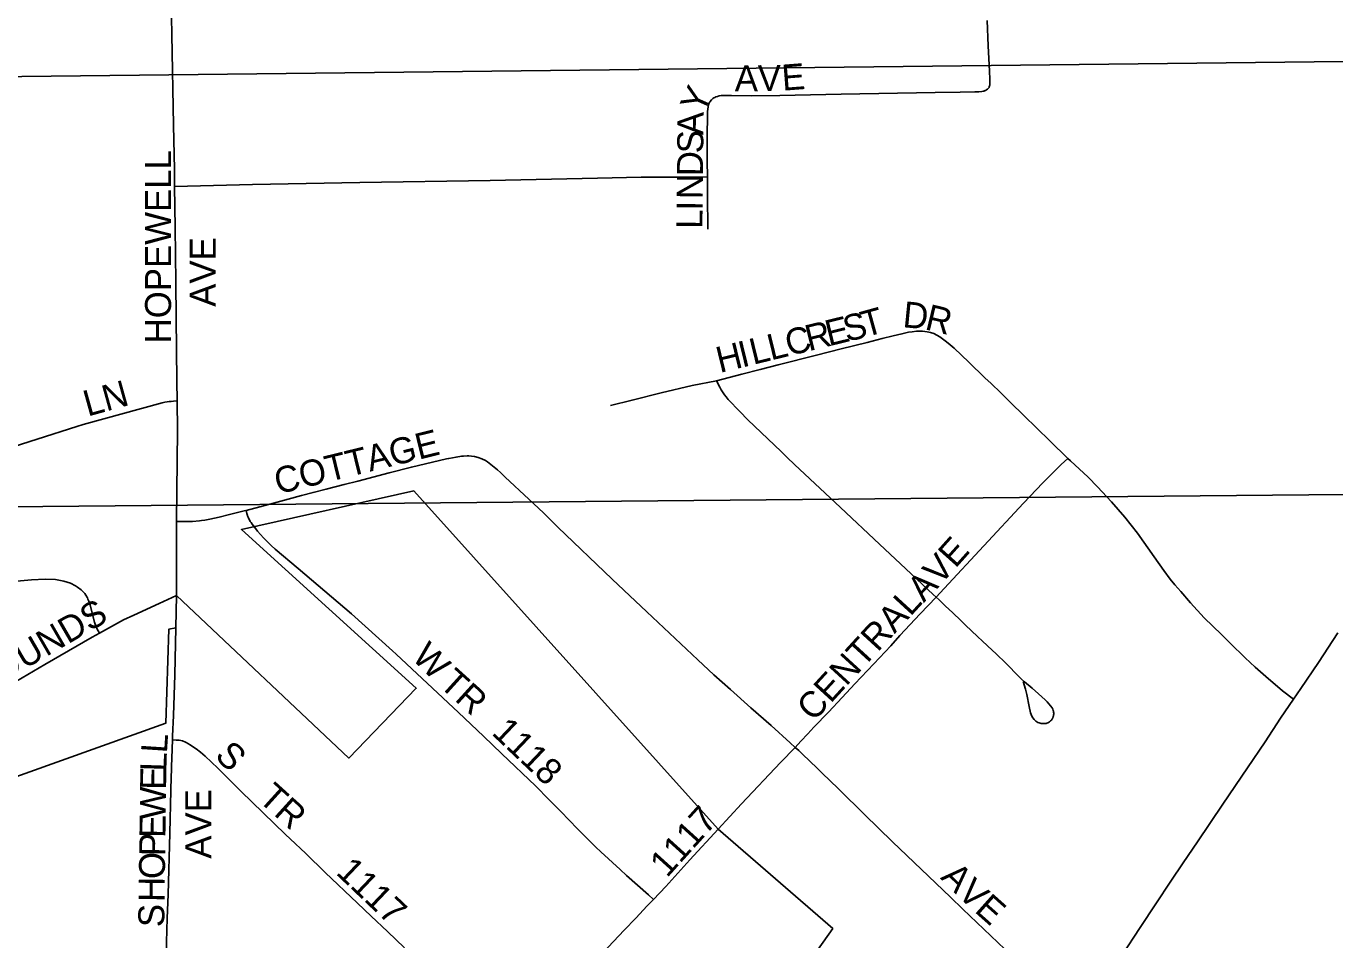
# Model space of a CAD drawing. Extents: x 0 to 34, y 0 to 22.
# Drawn here: x 5.2041 to 5.4422, y 18.3375 to 18.5038 of the extents above; entities that cross this region are included whole.
import ezdxf

# ---------------------------------------------------------------- set-up
doc = ezdxf.new("R2010")
doc.units = 0
for name, color, linetype in [('GM_X_City_Street', 7, 'Continuous'), ('GM_X_City_Street_Text', 7, 'Continuous'), ('GM_X_Corporation', 7, 'Continuous'), ('GM_X_Section', 7, 'Continuous'), ('GM_X_State_Route', 7, 'Continuous')]:
    doc.layers.add(name, color=color, linetype=linetype)

msp = doc.modelspace()

# ---------------------------------------------------------------- linework, layer by layer
at = {"layer": 'GM_X_City_Street'}
for points in [[(5.23109, 18.47463), (5.23105, 18.47771), (5.23086, 18.48578), (5.2306, 18.50224), (5.23035, 18.51491), (5.23033, 18.52348)], [(5.32805, 18.47635), (5.32797, 18.47924), (5.32797, 18.4837), (5.32802, 18.48767), (5.32805, 18.48826), (5.32808, 18.48868), (5.32813, 18.48907), (5.32817, 18.48927), (5.32822, 18.48944), (5.32831, 18.48967), (5.32836, 18.4898), (5.32845, 18.48995), (5.32853, 18.49008), (5.32874, 18.49034), (5.32887, 18.49048), (5.32894, 18.49055), (5.32903, 18.49062), (5.32919, 18.49073), (5.32935, 18.49082), (5.32954, 18.4909), (5.32984, 18.491), (5.33017, 18.49108), (5.33052, 18.49114), (5.3313, 18.49118), (5.3324, 18.49116), (5.33599, 18.49112), (5.3412, 18.49114), (5.35237, 18.4914), (5.36947, 18.4917), (5.37403, 18.49174), (5.37668, 18.49181), (5.37743, 18.49185), (5.37793, 18.49191), (5.3782, 18.49195), (5.37832, 18.49197), (5.37843, 18.492), (5.37854, 18.49205), (5.37863, 18.49209), (5.37878, 18.49218), (5.37885, 18.49223), (5.37897, 18.49233), (5.37915, 18.49249), (5.37926, 18.49264), (5.37931, 18.49275), (5.37936, 18.49289), (5.37938, 18.49297), (5.37941, 18.49317), (5.37942, 18.49335), (5.37942, 18.49368), (5.3794, 18.49412), (5.37932, 18.4956), (5.37909, 18.50017), (5.37894, 18.50481)], [(5.23109, 18.47463), (5.24526, 18.47497), (5.26478, 18.47533), (5.28848, 18.47569), (5.30805, 18.47614), (5.31598, 18.47629), (5.32367, 18.47633), (5.32805, 18.47635)], [(5.32808, 18.46682), (5.32805, 18.47302), (5.32805, 18.47635)], [(5.23154, 18.43559), (5.23151, 18.43918), (5.23137, 18.45068), (5.23132, 18.4572), (5.23121, 18.46715), (5.23109, 18.47463)], [(5.32968, 18.43927), (5.33311, 18.44014), (5.3343, 18.44046), (5.3376, 18.44131), (5.34091, 18.44214), (5.34789, 18.44393), (5.35236, 18.44505), (5.35707, 18.44623), (5.35984, 18.44692), (5.36184, 18.44741), (5.36341, 18.44777), (5.36462, 18.44807), (5.36529, 18.44818), (5.36606, 18.44826), (5.36662, 18.44829), (5.36717, 18.44829), (5.36799, 18.44819), (5.36862, 18.44805), (5.3692, 18.44783), (5.36977, 18.44755), (5.37029, 18.44722), (5.37129, 18.44652), (5.37184, 18.4461), (5.37291, 18.44519), (5.37559, 18.44262), (5.37851, 18.43982), (5.37964, 18.43878), (5.38141, 18.43704), (5.38317, 18.43529), (5.38562, 18.43291), (5.3903, 18.42834), (5.39359, 18.42514)], [(5.31041, 18.43474), (5.31431, 18.43575), (5.31962, 18.43704), (5.32526, 18.43841), (5.32968, 18.43927)], [(5.36965, 18.39989), (5.36912, 18.4004), (5.3651, 18.40414), (5.35931, 18.4095), (5.35222, 18.41621), (5.34387, 18.424), (5.34254, 18.4253), (5.34143, 18.42637), (5.33539, 18.43215), (5.3339, 18.43365), (5.33179, 18.43587), (5.33142, 18.43632), (5.33114, 18.43668), (5.33075, 18.43727), (5.33052, 18.43762), (5.33027, 18.43807), (5.32968, 18.43927)], [(5.15883, 18.41028), (5.16291, 18.41201), (5.16465, 18.41274), (5.16787, 18.41411), (5.17301, 18.41628), (5.18117, 18.41967), (5.18269, 18.42027), (5.18973, 18.42308), (5.19879, 18.42632), (5.21328, 18.43093), (5.21446, 18.43127), (5.22885, 18.43523), (5.22932, 18.43534), (5.22971, 18.43542), (5.23007, 18.43547), (5.23047, 18.4355), (5.23088, 18.43553), (5.23154, 18.43559)], [(5.23145, 18.41364), (5.23159, 18.43018), (5.23154, 18.43559)], [(5.24413, 18.41566), (5.24905, 18.41697), (5.25173, 18.4177), (5.2542, 18.41838), (5.25629, 18.41894), (5.25864, 18.41955), (5.26193, 18.42037), (5.26443, 18.421), (5.27012, 18.42248), (5.27417, 18.42354), (5.28054, 18.42505), (5.28096, 18.42514), (5.28229, 18.42538), (5.28326, 18.42552), (5.28363, 18.42555), (5.28431, 18.42559), (5.28461, 18.42558), (5.2851, 18.42554), (5.28567, 18.42545), (5.28634, 18.42528), (5.28699, 18.42505), (5.28763, 18.42472), (5.28801, 18.42448), (5.28831, 18.42426), (5.28983, 18.42304), (5.29038, 18.42256), (5.29124, 18.42174), (5.29554, 18.41772), (5.29821, 18.4152), (5.30083, 18.4126), (5.3107, 18.40319), (5.3128, 18.40115), (5.31698, 18.3972), (5.32625, 18.38849), (5.32922, 18.38577), (5.33222, 18.38308), (5.33591, 18.37978), (5.33965, 18.37651), (5.34307, 18.3734), (5.34401, 18.37254)], [(5.36965, 18.39989), (5.37111, 18.40148), (5.38555, 18.417), (5.38902, 18.42067), (5.39177, 18.42342), (5.39237, 18.42401), (5.39359, 18.42514)], [(5.39359, 18.42514), (5.39409, 18.42466), (5.39727, 18.4217), (5.39902, 18.41994), (5.40156, 18.41725), (5.40398, 18.41445), (5.40629, 18.41155), (5.40932, 18.40722), (5.41104, 18.40475), (5.41223, 18.40318), (5.41306, 18.40215), (5.41413, 18.40089), (5.41592, 18.39887), (5.41841, 18.39614), (5.42158, 18.39307), (5.42314, 18.39153), (5.42589, 18.38886), (5.42771, 18.38716), (5.42965, 18.38543), (5.43264, 18.38287), (5.43465, 18.38131)], [(5.23145, 18.41364), (5.23204, 18.41364), (5.23317, 18.41364), (5.23432, 18.41367), (5.23563, 18.41378), (5.23597, 18.41382), (5.23658, 18.41391), (5.23749, 18.41406), (5.23918, 18.41442), (5.24106, 18.4149), (5.24375, 18.41558), (5.24413, 18.41566)], [(5.24413, 18.41566), (5.24425, 18.41512), (5.24429, 18.41495), (5.24434, 18.41476), (5.24437, 18.41466), (5.2444, 18.41457), (5.24446, 18.41445), (5.24455, 18.41427), (5.2447, 18.41395), (5.24486, 18.41366), (5.24499, 18.41345), (5.24519, 18.41314), (5.24566, 18.41254), (5.24618, 18.4119), (5.24726, 18.4107), (5.24795, 18.40999), (5.24865, 18.40928), (5.24941, 18.40859), (5.25358, 18.40513), (5.26327, 18.39686), (5.27072, 18.39015), (5.27142, 18.38949), (5.28276, 18.37889), (5.28727, 18.3746)], [(5.23142, 18.4002), (5.23143, 18.40065), (5.23141, 18.40905), (5.23145, 18.41364)], [(5.1998, 18.40254), (5.20507, 18.40306), (5.20755, 18.40318), (5.20942, 18.40309), (5.21094, 18.40282), (5.21212, 18.40241), (5.21303, 18.40194), (5.21344, 18.40168), (5.21409, 18.40119), (5.21434, 18.40096), (5.21474, 18.40053), (5.21495, 18.40023), (5.21521, 18.39979), (5.21532, 18.39952), (5.21546, 18.39917), (5.2157, 18.39843), (5.21652, 18.39533), (5.21664, 18.39496), (5.21686, 18.39439), (5.21702, 18.39404), (5.21718, 18.39375), (5.21744, 18.39335)], [(5.22366, 18.39662), (5.22828, 18.39875), (5.23142, 18.4002)], [(5.23071, 18.37392), (5.23073, 18.3746), (5.23086, 18.37833), (5.23113, 18.38578), (5.23132, 18.39433), (5.23142, 18.4002)], [(5.34401, 18.37254), (5.34505, 18.3737), (5.34629, 18.375), (5.34739, 18.37621), (5.35006, 18.37899), (5.35252, 18.38161), (5.35483, 18.38412), (5.35828, 18.38778), (5.36138, 18.39103), (5.36306, 18.39289), (5.36675, 18.39687), (5.36965, 18.39989)], [(5.38546, 18.38457), (5.3859, 18.38313), (5.38615, 18.38216), (5.38654, 18.38001), (5.38682, 18.37885), (5.38707, 18.37823), (5.38725, 18.37791), (5.38747, 18.3776), (5.38777, 18.37732), (5.38812, 18.3771), (5.38839, 18.377), (5.38873, 18.37692), (5.38915, 18.37688), (5.38934, 18.37688), (5.38963, 18.37693), (5.38977, 18.37697), (5.38993, 18.37703), (5.39007, 18.3771), (5.39027, 18.37722), (5.39046, 18.37736), (5.39061, 18.37752), (5.39075, 18.37772), (5.39084, 18.3779), (5.39094, 18.37815), (5.39098, 18.37827), (5.39099, 18.37833), (5.39101, 18.37846), (5.39103, 18.37862), (5.39103, 18.37881), (5.39101, 18.37896), (5.39098, 18.37915), (5.39095, 18.37929), (5.39087, 18.37949), (5.39072, 18.37976), (5.39046, 18.38011), (5.38981, 18.38082), (5.38947, 18.38118), (5.38829, 18.3823), (5.38708, 18.38335), (5.3857, 18.38449), (5.38518, 18.38496), (5.38477, 18.38538), (5.38231, 18.38786), (5.38054, 18.38959), (5.37986, 18.39022), (5.37808, 18.3919), (5.37718, 18.39271), (5.37609, 18.39378), (5.37499, 18.39479), (5.37413, 18.39563), (5.37266, 18.39701), (5.3713, 18.3983), (5.37019, 18.39938), (5.36965, 18.39989)], [(5.21744, 18.39335), (5.22067, 18.39518), (5.22177, 18.39575), (5.22366, 18.39662)], [(5.19889, 18.38266), (5.20232, 18.38463), (5.20746, 18.38763), (5.21611, 18.3926), (5.21744, 18.39335)], [(5.23181, 18.32496), (5.23143, 18.32555), (5.23108, 18.32616), (5.2308, 18.32675), (5.23053, 18.32748), (5.23031, 18.32822), (5.2301, 18.32911), (5.2299, 18.33018), (5.22981, 18.33083), (5.22974, 18.33157), (5.22963, 18.33388), (5.22961, 18.3371), (5.22973, 18.34147), (5.2299, 18.3458), (5.23022, 18.35696), (5.2304, 18.36471), (5.23048, 18.3672), (5.23051, 18.36844), (5.23052, 18.36906), (5.23059, 18.37059), (5.23071, 18.37392)], [(5.23071, 18.37392), (5.23137, 18.37388), (5.23176, 18.37386), (5.23194, 18.37384), (5.2322, 18.3738), (5.23251, 18.37373), (5.23265, 18.37368), (5.23297, 18.37356), (5.23318, 18.37345), (5.23359, 18.37322), (5.23379, 18.37309), (5.23501, 18.3723), (5.23581, 18.37168), (5.23662, 18.37098), (5.23892, 18.36877), (5.24316, 18.36457), (5.25127, 18.3567), (5.2521, 18.35593), (5.25496, 18.35322), (5.25848, 18.3498), (5.26439, 18.3442), (5.26686, 18.34185), (5.26979, 18.33907), (5.2729, 18.33607)], [(5.28727, 18.3746), (5.29063, 18.37139), (5.29672, 18.36557), (5.29926, 18.36304), (5.30136, 18.36088), (5.3044, 18.35773), (5.30648, 18.35563), (5.30775, 18.35438), (5.30862, 18.35358), (5.31216, 18.35031), (5.31333, 18.34924), (5.31731, 18.34571), (5.31822, 18.3449)], [(5.32998, 18.35768), (5.3342, 18.36227), (5.34134, 18.36982), (5.34401, 18.37254)], [(5.34401, 18.37254), (5.34464, 18.37196), (5.34532, 18.37133), (5.34797, 18.36876), (5.34908, 18.3677), (5.3502, 18.36663), (5.35199, 18.36491), (5.35663, 18.36036), (5.36172, 18.35538), (5.36822, 18.34915), (5.37226, 18.3453), (5.37449, 18.34313), (5.38214, 18.33587), (5.38327, 18.33481), (5.38735, 18.33103), (5.38872, 18.32979), (5.39099, 18.32771), (5.39266, 18.32638), (5.39411, 18.32534), (5.39537, 18.32459), (5.39631, 18.32403)], [(5.31822, 18.3449), (5.32045, 18.34722), (5.32484, 18.35207), (5.32998, 18.35768)], [(5.29316, 18.32001), (5.2938, 18.32024), (5.29417, 18.32043), (5.29471, 18.32079), (5.29555, 18.32142), (5.29625, 18.32198), (5.29768, 18.32335), (5.29955, 18.32544), (5.30187, 18.32791), (5.30334, 18.32942), (5.30553, 18.3316), (5.30994, 18.33621), (5.31288, 18.33929), (5.31498, 18.34148), (5.31707, 18.34371), (5.31822, 18.3449)]]:
    msp.add_lwpolyline(points, dxfattribs=at)
at = {"layer": 'GM_X_Corporation'}
msp.add_lwpolyline([(5.33764, 18.3209), (5.35084, 18.33959), (5.32998, 18.35768), (5.27459, 18.41921), (5.24324, 18.41219), (5.27506, 18.38332), (5.2628, 18.37062), (5.23142, 18.4002), (5.23133, 18.39433), (5.23006, 18.39408), (5.22948, 18.37696), (5.16013, 18.35215)], dxfattribs=at)
at = {"layer": 'GM_X_Section'}
for points in [[(4.96887, 18.91739), (5.22048, 18.91682), (5.36618, 18.91648), (5.36674, 18.86475), (5.0257, 18.8658), (5.02156, 18.49258), (5.46515, 18.49757), (5.46379, 18.41876), (4.95692, 18.41406)], [(5.46396, 18.4161), (5.4644, 17.92291), (5.46435, 17.9159), (4.95614, 17.90875), (4.95692, 18.41406), (5.46379, 18.41876)]]:
    msp.add_lwpolyline(points, close=True, dxfattribs=at)
at = {"layer": 'GM_X_State_Route'}
msp.add_lwpolyline([(5.40344, 18.33469), (5.40675, 18.33979), (5.4096, 18.34409), (5.41232, 18.34822), (5.41459, 18.35153), (5.41717, 18.35539), (5.42182, 18.36224), (5.42626, 18.36885), (5.4295, 18.37357), (5.43226, 18.37786), (5.43465, 18.38131), (5.43601, 18.38329), (5.43918, 18.38798), (5.44274, 18.39337)], dxfattribs=at)

# ---------------------------------------------------------------- texts
at = {"layer": 'GM_X_City_Street_Text'}
for s, height, rotation, p in [('A', 0.00473, 0.0874, (5.333, 18.49194)), ('V', 0.00473, 0.9054, (5.33723, 18.49194)), ('E', 0.00473, 4.4187, (5.34172, 18.49202)), ('Y', 0.00473, 66.1041, (5.32722, 18.48762)), ('A', 0.00473, 89.3846, (5.32728, 18.48395)), ('S', 0.00473, 89.3928, (5.32725, 18.48062)), ('HOPEWELL', 0.004735, 90, (5.23044, 18.44605)), ('D', 0.00473, 89.3846, (5.3272, 18.47645)), ('N', 0.00473, 89.3846, (5.32716, 18.47228)), ('L', 0.00473, 89.3989, (5.3271, 18.46687)), ('I', 0.00473, 89.3882, (5.32714, 18.4702)), ('AVE', 0.004735, 90, (5.23858, 18.45271)), ('T', 0.00473, 15.4331, (5.35672, 18.44714)), ('D', 0.00473, 354.483, (5.36344, 18.44902)), ('R', 0.00473, 346.4174, (5.36742, 18.44865)), ('E', 0.00473, 13.738, (5.3501, 18.44551)), ('S', 0.00473, 13.7685, (5.35334, 18.4463)), ('L', 0.00473, 13.7438, (5.33958, 18.44294)), ('C', 0.00473, 13.7572, (5.34282, 18.44373)), ('R', 0.00473, 13.7536, (5.34646, 18.44462)), ('H', 0.00473, 13.75, (5.33027, 18.44066)), ('I', 0.00473, 13.7544, (5.33432, 18.44165)), ('L', 0.00473, 13.738, (5.33634, 18.44215)), ('LN', 0.004735, 15.526, (5.21526, 18.43272)), ('COTTAGE', 0.004735, 13.824, (5.24988, 18.41858)), ('E', 0.00473, 48.1851, (5.37313, 18.40501)), ('V', 0.00473, 48.0297, (5.37034, 18.4019)), ('A', 0.00473, 46.6233, (5.36739, 18.39878)), ('CENTRAL', 0.004735, 47.4873, (5.34734, 18.37707)), ('FAIRGROUNDS', 0.0047348, 30.0928, (5.1788, 18.37224)), ('W', 0.00473, 315.0121, (5.27404, 18.38876)), ('TR', 0.004735, 317.8608, (5.27901, 18.38379)), ('1118', 0.004735, 316.4679, (5.28861, 18.37503)), ('L', 0.00473, 86.3367, (5.22968, 18.37142)), ('S', 0.00473, 315, (5.23821, 18.37084)), ('L', 0.00473, 88.1145, (5.22957, 18.36812)), ('E', 0.00473, 89.2077, (5.22953, 18.36481)), ('W', 0.00473, 89.2197, (5.22946, 18.3594)), ('AVE', 0.004735, 90, (5.23775, 18.3523)), ('TR', 0.004735, 317.8608, (5.24609, 18.36296)), ('1117', 0.004735, 47.864, (5.32065, 18.34871)), ('E', 0.00473, 89.2047, (5.22941, 18.35606)), ('P', 0.00473, 89.2047, (5.22936, 18.35273)), ('O', 0.00473, 89.2045, (5.22931, 18.34857)), ('1117', 0.004735, 316.4737, (5.26027, 18.34961)), ('A', 0.00473, 315.0773, (5.37029, 18.34876)), ('H', 0.00473, 89.2045, (5.22925, 18.3444)), ('V', 0.00473, 316.2102, (5.37331, 18.34574)), ('E', 0.00473, 318.2205, (5.37645, 18.34274)), ('S', 0.00473, 89.2077, (5.22919, 18.33982))]:
    msp.add_text(s, height=height, rotation=rotation, dxfattribs=at).set_placement(p)

doc.saveas('drawing.dxf')
